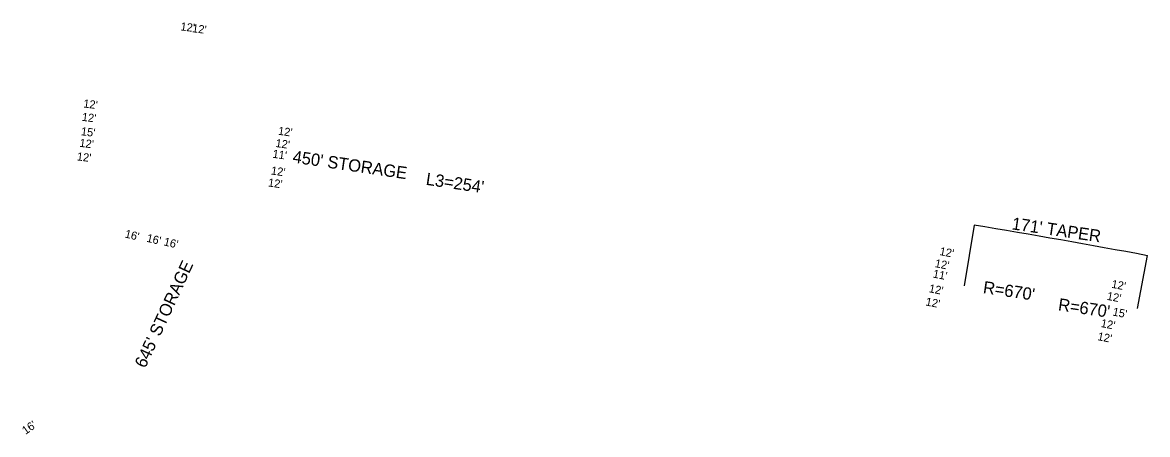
# Model space of a CAD drawing. Extents: x 1938746 to 1943895, y 778846 to 782535.
# Drawn here: x 1942794 to 1943895, y 779817 to 780220 of the extents above; entities that cross this region are included whole.
import ezdxf

# ---------------------------------------------------------------- set-up
doc = ezdxf.new("R2010")
doc.units = 0
doc.layers.add('RD_PD_Final_TX', color=7, linetype='Continuous')

msp = doc.modelspace()

# ---------------------------------------------------------------- linework, layer by layer
at = {"layer": 'RD_PD_Final_TX'}
for p, q in [((1943725, 780021.3), (1943715.2, 779962)), ((1943885, 779939.9), (1943894.7, 779991.5))]:
    msp.add_line(p, q, dxfattribs=at)
msp.add_arc((1942437, 772196.6), 7930, 79.40816, 80.65309, dxfattribs=at)

# ---------------------------------------------------------------- texts
for s, height, rotation, p in [("12'", 8, 352.9935, (1942948.2, 780212)), ("12'", 8, 352.9935, (1942959.6, 780210.2)), ("12'", 8, 352.9935, (1942853.1, 780136.6)), ("12'", 8, 352.9935, (1942851.7, 780123.5)), ("15'", 8, 352.9935, (1942850.8, 780109.4)), ("12'", 8, 351.907, (1943043.6, 780109.9)), ("12'", 8, 352.9935, (1942849.3, 780098.1)), ("12'", 8, 351.907, (1943041.1, 780097.9)), ("11'", 8, 351.907, (1943038.2, 780087.4)), ("450' STORAGE", 12, 351.6098, (1943057.7, 780082.7)), ("12'", 8, 352.9935, (1942846.8, 780084.8)), ("12'", 8, 351.907, (1943036.7, 780071)), ("L3=254'", 12, 351.6098, (1943188.1, 780060.9)), ("12'", 8, 351.907, (1943033.8, 780059.3)), ("171' TAPER", 12, 351.6098, (1943761.3, 780017.3)), ("16'", 8, 346.1985, (1942893.5, 780009.4)), ("16'", 8, 346.9849, (1942914.8, 780005.2)), ("16'", 8, 346.5512, (1942931.6, 780001.7)), ("12'", 8, 348.9848, (1943690.7, 779992.2)), ("645' STORAGE", 12, 65.1534, (1942914, 779880.7)), ("12'", 8, 348.9848, (1943686.1, 779980.4)), ("11'", 8, 348.9848, (1943684.2, 779970.2)), ("12'", 8, 348.9848, (1943680.3, 779955.8)), ("R=670'", 12, 351.6098, (1943733.2, 779954.9)), ("12'", 8, 348.9848, (1943858.9, 779960.2)), ("12'", 8, 348.9848, (1943677.1, 779942.9)), ("R=670'", 12, 351.6098, (1943806.7, 779938.1)), ("12'", 8, 348.9848, (1943854.4, 779948.4)), ("15'", 8, 348.9848, (1943860.1, 779933)), ("12'", 8, 348.9848, (1943848.5, 779921.8)), ("12'", 8, 348.9848, (1943845.3, 779908.9)), ("16'", 8, 34.7104, (1942796.9, 779816.1))]:
    msp.add_text(s, height=height, rotation=rotation, dxfattribs=at).set_placement(p)

doc.saveas('drawing.dxf')
